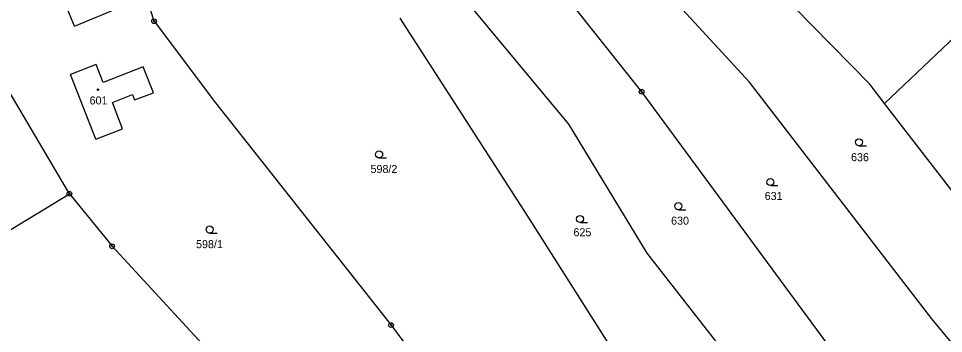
# Model space of a CAD drawing. Extents: x -445050 to -440454, y -1134563 to -1129741.
# Drawn here: x -441906.2 to -441709.8, y -1132022.5 to -1131955.6 of the extents above; entities that cross this region are included whole.
import ezdxf

# ---------------------------------------------------------------- set-up
doc = ezdxf.new("R2010")
doc.units = 0
for name, color, linetype in [('Vrstva 1', 7, 'Continuous'), ('Vrstva 18', 7, 'Continuous'), ('Vrstva 19', 7, 'Continuous'), ('Vrstva 24', 7, 'Continuous'), ('Vrstva 25', 7, 'Continuous'), ('Vrstva 3', 7, 'Continuous'), ('Vrstva 37', 7, 'Continuous')]:
    doc.layers.add(name, color=color, linetype=linetype)

msp = doc.modelspace()

# ---------------------------------------------------------------- linework, layer by layer
at = {"layer": 'Vrstva 1'}
for points in [[(-441877.37, -1131956.18), (-441884.55, -1131933.7)], [(-441782.69, -1131934.59), (-441750.97, -1131969.09)], [(-441725.42, -1131969.57), (-441757.78, -1131936.53)], [(-441795.7, -1131943.65), (-441773.87, -1131971.14)], [(-441894.25, -1131957.22), (-441898.86, -1131946.09)], [(-441812.1, -1131950.63), (-441789.42, -1131978.02)], [(-441894.25, -1131957.22), (-441884.72, -1131953.27)], [(-441877.37, -1131956.18), (-441864.32, -1131973.53)], [(-441798.18, -1131997.41), (-441825.16, -1131955.48)], [(-441705.83, -1131957.99), (-441722.29, -1131973.62)], [(-441895.36, -1131992.82), (-441913.3, -1131962.46)], [(-441889.68, -1131965.38), (-441895.11, -1131967.49)], [(-441888.21, -1131969.16), (-441889.68, -1131965.38)], [(-441879.68, -1131965.85), (-441888.21, -1131969.16)], [(-441877.54, -1131971.35), (-441879.68, -1131965.85)], [(-441889.76, -1131981.26), (-441895.11, -1131967.49)], [(-441712.24, -1132019.44), (-441750.97, -1131969.09)], [(-441722.29, -1131973.62), (-441725.42, -1131969.57)], [(-441886.24, -1131973.41), (-441881.96, -1131971.75)], [(-441881.96, -1131971.75), (-441881.51, -1131972.89)], [(-441881.51, -1131972.89), (-441877.54, -1131971.35)], [(-441773.87, -1131971.14), (-441723.5, -1132039.66)], [(-441884.06, -1131979.04), (-441886.24, -1131973.41)], [(-441864.32, -1131973.53), (-441827.07, -1132020.75)], [(-441683.82, -1132023.42), (-441722.29, -1131973.62)], [(-441789.42, -1131978.02), (-441772.79, -1132005.47)], [(-441889.76, -1131981.26), (-441884.06, -1131979.04)], [(-441941.24, -1132020.73), (-441895.36, -1131992.82)], [(-441895.36, -1131992.82), (-441886.3, -1132004)], [(-441776.67, -1132031.29), (-441798.18, -1131997.41)], [(-441886.3, -1132004), (-441860.59, -1132031.89)], [(-441772.79, -1132005.47), (-441745.51, -1132040.36)], [(-441827.07, -1132020.75), (-441807.08, -1132047.52)], [(-441698.86, -1132035.54), (-441712.24, -1132019.44)]]:
    msp.add_lwpolyline(points, dxfattribs=at)
at = {"layer": 'Vrstva 24'}
for centre, radius in [((-441877.37, -1131956.18), 0.5), ((-441877.37, -1131956.18), 0.1), ((-441773.87, -1131971.14), 0.5), ((-441773.87, -1131971.14), 0.1), ((-441895.36, -1131992.82), 0.5), ((-441895.36, -1131992.82), 0.1), ((-441886.3, -1132004), 0.5), ((-441886.3, -1132004), 0.1), ((-441827.07, -1132020.75), 0.5), ((-441827.07, -1132020.75), 0.1)]:
    msp.add_circle(centre, radius, dxfattribs=at)
at = {"layer": 'Vrstva 25'}
for p, q in [((-441727.72, -1131982.64), (-441726.12, -1131982.64)), ((-441829.61, -1131985.23), (-441828.01, -1131985.23)), ((-441746.54, -1131991.09), (-441744.94, -1131991.09)), ((-441766.07, -1131996.22), (-441764.47, -1131996.22)), ((-441786.94, -1131998.94), (-441785.34, -1131998.94)), ((-441865.59, -1132001.18), (-441863.99, -1132001.18))]:
    msp.add_line(p, q, dxfattribs=at)
for centre, radius in [((-441889.28, -1131970.7), 0.175), ((-441727.72, -1131981.89), 0.75), ((-441829.61, -1131984.48), 0.75), ((-441746.54, -1131990.34), 0.75), ((-441766.07, -1131995.47), 0.75), ((-441786.94, -1131998.19), 0.75), ((-441865.59, -1132000.43), 0.75)]:
    msp.add_circle(centre, radius, dxfattribs=at)
at = {"layer": 'Vrstva 3'}
for points in [[(-441894.25, -1131957.22), (-441898.86, -1131946.09)], [(-441894.25, -1131957.22), (-441884.72, -1131953.27)], [(-441889.68, -1131965.38), (-441895.11, -1131967.49)], [(-441888.21, -1131969.16), (-441889.68, -1131965.38)], [(-441879.68, -1131965.85), (-441888.21, -1131969.16)], [(-441877.54, -1131971.35), (-441879.68, -1131965.85)], [(-441889.76, -1131981.26), (-441895.11, -1131967.49)], [(-441886.24, -1131973.41), (-441881.96, -1131971.75)], [(-441881.96, -1131971.75), (-441881.51, -1131972.89)], [(-441881.51, -1131972.89), (-441877.54, -1131971.35)], [(-441884.06, -1131979.04), (-441886.24, -1131973.41)], [(-441889.76, -1131981.26), (-441884.06, -1131979.04)]]:
    msp.add_lwpolyline(points, dxfattribs=at)
at = {"layer": 'Vrstva 37'}
msp.add_circle((-441889.28, -1131970.7), 0.175, dxfattribs=at)

# ---------------------------------------------------------------- texts
at = {"layer": 'Vrstva 18'}
for s, p in [('636', (-441729.4, -1131985.91)), ('598/2', (-441831.42, -1131988.41)), ('631', (-441747.74, -1131994.16)), ('630', (-441767.61, -1131999.4)), ('625', (-441788.33, -1132001.86)), ('598/1', (-441868.47, -1132004.39))]:
    msp.add_text(s, height=1.7, dxfattribs=at).set_placement(p)
at = {"layer": 'Vrstva 19'}
msp.add_text('601', height=1.7, dxfattribs=at).set_placement((-441891.07, -1131973.85))

doc.saveas('drawing.dxf')
